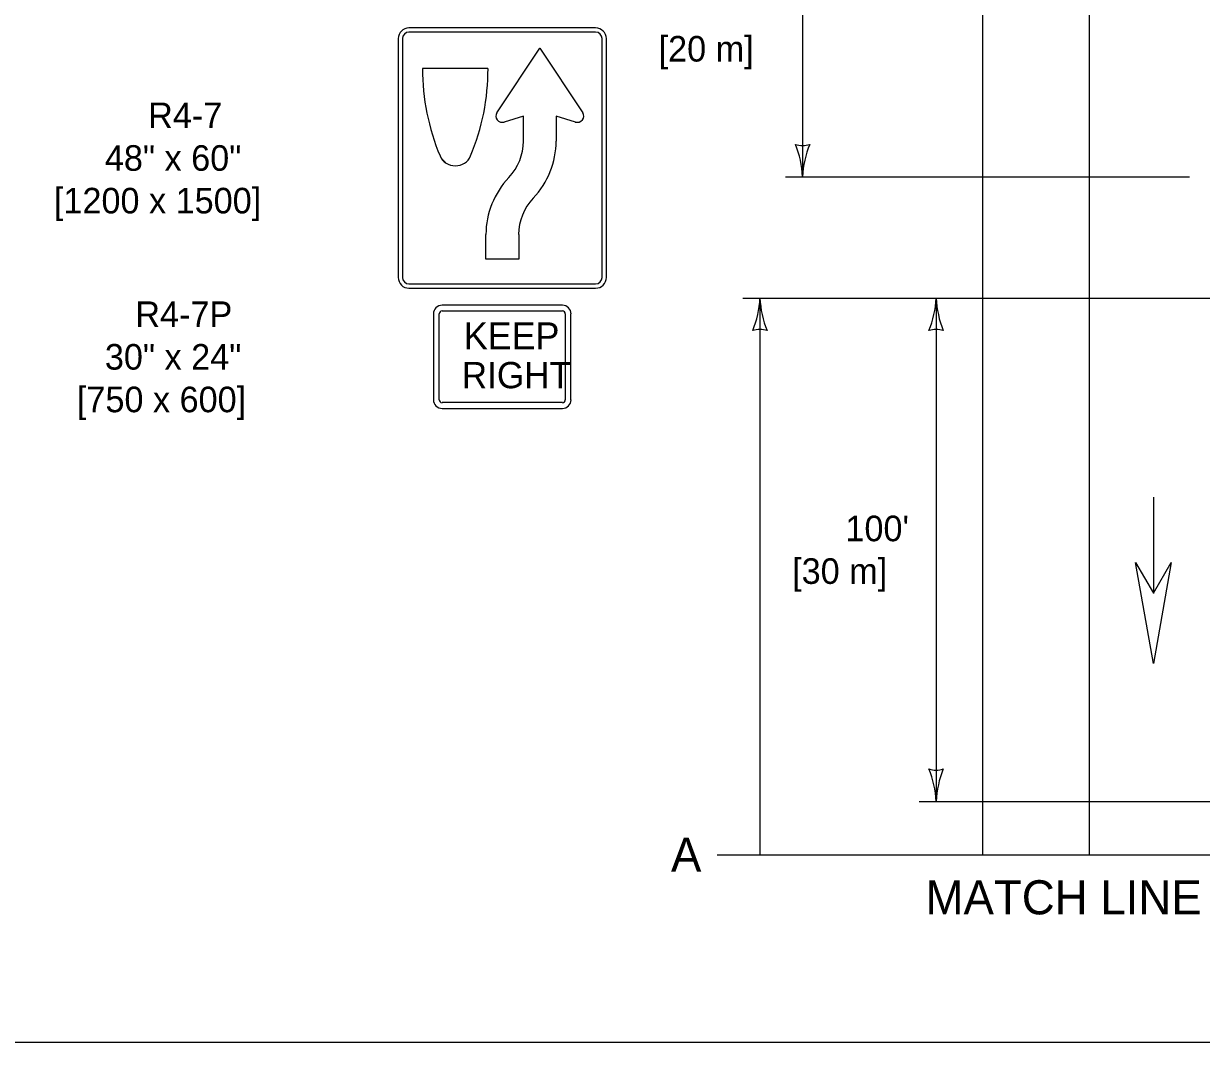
# Model space of a CAD drawing. Extents: x 49991.4 to 50021, y 49987.6 to 50011.4.
# Drawn here: x 50005.065 to 50007.828, y 49987.799 to 49990.189 of the extents above; entities that cross this region are included whole.
import ezdxf

# ---------------------------------------------------------------- set-up
doc = ezdxf.new("R2010")
doc.units = 0
for name, color, linetype in [('Level 1', 7, 'Continuous'), ('Level 2', 7, 'Continuous'), ('Level 3', 7, 'Continuous'), ('Level 6', 7, 'Continuous')]:
    doc.layers.add(name, color=color, linetype=linetype)

msp = doc.modelspace()

# ---------------------------------------------------------------- linework, layer by layer
at = {"layer": 'Level 1'}
for p, q in [((50007.315, 49988.2392), (50007.315, 49998.6725)), ((50007.565, 49988.2392), (50007.565, 49998.6725)), ((50006.4064, 49990.1787), (50005.9687, 49990.1787)), ((50006.4064, 49990.1685), (50005.9687, 49990.1685)), ((50005.9433, 49990.1533), (50005.9433, 49989.5934)), ((50005.9534, 49990.1533), (50005.9534, 49989.5934)), ((50006.4217, 49989.5934), (50006.4217, 49990.1533)), ((50006.4318, 49989.5934), (50006.4318, 49990.1533)), ((50006.1745, 49989.9792), (50006.2759, 49990.1311)), ((50006.2759, 49990.1311), (50006.3765, 49989.9792)), ((50006.1538, 49990.0836), (50006.0005, 49990.0836)), ((50006.1749, 49989.9792), (50006.1745, 49989.9792)), ((50006.2372, 49989.9715), (50006.1922, 49989.9576)), ((50006.2372, 49989.913), (50006.2372, 49989.9715)), ((50006.359, 49989.9576), (50006.3138, 49989.9715)), ((50006.3138, 49989.9715), (50006.3138, 49989.913)), ((50006.1493, 49989.6362), (50006.1493, 49989.6938)), ((50006.2262, 49989.6938), (50006.2262, 49989.6362)), ((50006.2262, 49989.6362), (50006.1493, 49989.6362)), ((50005.9687, 49989.5782), (50006.4064, 49989.5782)), ((50005.9687, 49989.568), (50006.4064, 49989.568)), ((50006.0263, 49989.5078), (50006.0263, 49989.3062)), ((50006.0397, 49989.3062), (50006.0397, 49989.5078)), ((50006.3287, 49989.528), (50006.0464, 49989.528)), ((50006.0464, 49989.5146), (50006.3287, 49989.5146)), ((50006.3354, 49989.5078), (50006.3354, 49989.3062)), ((50006.3488, 49989.3062), (50006.3488, 49989.5078)), ((50006.3287, 49989.2995), (50006.0464, 49989.2995)), ((50006.0464, 49989.2861), (50006.3287, 49989.2861)), ((50007.7149, 49989.078), (50007.7149, 49988.8522)), ((50007.7151, 49989.078), (50007.7151, 49988.8522))]:
    msp.add_line(p, q, dxfattribs=at)
for points in [[(49999.3835, 49998.9992), (50016.7501, 49998.9992), (50016.7501, 49987.7988), (49999.3835, 49987.7988)], [(50007.7569, 49988.9244), (50007.7151, 49988.688), (50007.6733, 49988.9244), (50007.7151, 49988.8524)]]:
    msp.add_lwpolyline(points, close=True, dxfattribs=at)
for points in [[(50006.2751, 49990.1311), (50006.2761, 49990.1299)], [(50006.0546, 49989.8626), (50006.0467, 49989.8703)]]:
    msp.add_lwpolyline(points, dxfattribs=at)
for centre, radius, start, end in [((50005.9688, 49990.1533), 0.0254, 90, 180), ((50005.9688, 49990.1533), 0.0153, 90, 180), ((50006.4064, 49990.1533), 0.0254, 360, 90), ((50006.4064, 49990.1533), 0.0153, 360, 90), ((50005.9688, 49989.5934), 0.0254, 180, 270), ((50005.9688, 49989.5934), 0.0153, 180, 270), ((50006.4064, 49989.5934), 0.0254, 270, 360), ((50006.4064, 49989.5934), 0.0153, 270, 360), ((50006.0464, 49989.5078), 0.0202, 90, 180), ((50006.0464, 49989.5078), 0.00672, 90, 180), ((50006.3287, 49989.5078), 0.0202, 0, 90), ((50006.3287, 49989.5078), 0.00672, 0, 90), ((50006.0464, 49989.3062), 0.0202, 180, 270), ((50006.0464, 49989.3062), 0.00672, 180, 270), ((50006.3287, 49989.3062), 0.00672, 270, 360), ((50006.3287, 49989.3062), 0.0202, 270, 360)]:
    msp.add_arc(centre, radius, start, end, dxfattribs=at)
for centre, major_axis, start_param, end_param in [((50006.576, 49990.0814), (0.5754, 0), 3.138019, 3.521863), ((50005.5788, 49990.0814), (0.5754, 0), 5.90292, 6.286763), ((50006.1877, 49989.9716), (-0.0152, 0), 5.720439, 8.161485), ((50006.3635, 49989.9716), (-0.0152, 0), 1.263276, 3.704354), ((50006.103, 49989.913), (0.1343, 0), 5.553465, 6.283185), ((50006.103, 49989.913), (0.211, 0), 5.553465, 6.283185), ((50006.0774, 49989.8917), (0.0384, 0), 3.521859, 5.902934), ((50006.3603, 49989.6939), (0.211, 0), 2.411875, 3.141593), ((50006.3603, 49989.6939), (0.1343, 0), 2.411875, 3.141593)]:
    msp.add_ellipse(centre, major_axis=major_axis, ratio=0.951905, start_param=start_param, end_param=end_param, dxfattribs=at)
at = {"layer": 'Level 3'}
for p, q in [((50006.892, 49990.5299), (50006.892, 49989.8293)), ((50006.852, 49989.8293), (50007.8, 49989.8293)), ((50006.752, 49989.5447), (50008.125, 49989.5447)), ((50006.792, 49989.5447), (50006.792, 49988.2392)), ((50007.2053, 49989.5447), (50007.2053, 49988.3642)), ((50007.1653, 49988.3642), (50008.125, 49988.3642))]:
    msp.add_line(p, q, dxfattribs=at)
for centre, radius, start, end in [((50006.6699, 49989.8201), 0.2223, 2.3605, 22.544), ((50006.892, 49989.9575), 0.0548, 252.1388, 287.8612), ((50007.1247, 49989.8178), 0.233, 157.9228, 177.1727), ((50006.5699, 49989.5539), 0.2223, 337.456, 357.6395), ((50007.0247, 49989.5562), 0.233, 182.8273, 202.0772), ((50006.9832, 49989.5539), 0.2223, 337.456, 357.6395), ((50007.438, 49989.5562), 0.233, 182.8273, 202.0772), ((50006.792, 49989.4165), 0.0548, 72.1388, 107.8612), ((50007.2053, 49989.4165), 0.0548, 72.1388, 107.8612), ((50006.9832, 49988.355), 0.2223, 2.3605, 22.544), ((50007.2053, 49988.4924), 0.0548, 252.1388, 287.8612), ((50007.438, 49988.3527), 0.233, 157.9228, 177.1727)]:
    msp.add_arc(centre, radius, start, end, dxfattribs=at)
at = {"layer": 'Level 6'}
msp.add_line((50006.692, 49988.2392), (50008.365, 49988.2392), dxfattribs=at)

# ---------------------------------------------------------------- texts
at = {"layer": 'Level 1'}
for s, height, p in [('KEEP', 0.06284, (50006.0975, 49989.4249)), ('RIGHT', 0.06165, (50006.0925, 49989.3333))]:
    msp.add_text(s, height=height, rotation=360, dxfattribs=at).set_placement(p)
at = {"layer": 'Level 2'}
for s, height, p in [('[20 m]', 0.06, (50006.5543, 49990.0996)), ('R4-7', 0.06, (50005.3569, 49989.9434)), ('48" x 60"', 0.06, (50005.2554, 49989.8434)), ('[1200 x 1500]', 0.06, (50005.1359, 49989.7434)), ('R4-7P', 0.06, (50005.3269, 49989.477)), ('30" x 24"', 0.06, (50005.2554, 49989.377)), ('[750 x 600]', 0.06, (50005.1898, 49989.277)), ("100'", 0.06, (50006.9925, 49988.9744)), ('[30 m]', 0.06, (50006.8676, 49988.8744)), ('A', 0.08, (50006.5833, 49988.1992)), ('MATCH LINE', 0.08, (50007.1804, 49988.0992))]:
    msp.add_text(s, height=height, dxfattribs=at).set_placement(p)

doc.saveas('drawing.dxf')
